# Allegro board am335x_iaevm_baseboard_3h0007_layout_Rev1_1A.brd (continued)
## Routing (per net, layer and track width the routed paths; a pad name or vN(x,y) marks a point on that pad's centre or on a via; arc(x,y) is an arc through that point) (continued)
LCD_DATA19: length 30.1
  TOP w0.121: R264.1 112.41,86.12 115,86.12 115.18,85.94 116.82,85.94 116.82,85.94 117.19,85.94 117.19,85.94 117.68,85.94 118.33,85.29 v1(118.77,85.29)
  LY3 w0.102: 130.63,79.96 131.03,79.56 133.16,79.56 133.82,78.9 J7.13
  LY3 w0.133: 130.63,79.96 129.88,80.71 129.09,80.71 126.55,83.25 126.55,85.91 125.34,87.13 122.06,87.13 120.22,85.29 v1(118.77,85.29)
LCD_DATA20: length 26.6
  TOP w0.102: 130.72,85.25 J8.3
  TOP w0.121: 130.72,85.25 130.59,85.25 130.28,84.95 128.75,84.95 128.18,85.52 128.18,87.41 127.93,87.67 125.8,87.67 122.19,84.05 112.48,84.05 112.36,83.93 112.36,83.6 112.48,83.48 112.72,83.48 112.84,83.36 112.84,83.07 112.48,82.71 R243.1
LCD_DATA21: length 35.6
  TOP w0.102: 130.72,85.89 132.12,85.89 J8.4
  TOP w0.121: R242.1 111.34,85.76 111.84,85.26 112.3,85.26 112.74,85.69 116.72,85.69 116.72,85.69 117.21,85.69 117.33,85.57 117.33,85.15 117.21,85.03 114.08,85.03 113.96,84.9 113.96,84.69 114.34,84.3 122.09,84.3 125.7,87.92 128.06,87.92 128.31,87.67 128.31,87.64 128.43,87.52 128.43,85.73 128.96,85.19 130.02,85.19 130.72,85.89
LCD_DATA22: length 50.4
  TOP w0.121: R263.1 v1(104.81,91.6)
  LY3 w0.133: v1(137.36,91.12) 138.72,91.12 139.83,90.01 139.85,90.01 139.85,89.96 v1(140.17,89.65)
  BOTTOM w0.102: 138.04,78.9 J7.14
  BOTTOM w0.121: v1(140.17,89.65) 140.17,88.83 140.12,88.78 140.12,80.99 138.04,78.9 ; v1(104.81,91.6) 107.92,91.6 108.69,90.84 124.79,90.84 125.3,90.33 128.68,90.33 129.12,90.77 132.05,90.77 132.49,90.33 136.56,90.33 137.35,91.12 v1(137.36,91.12)
LCD_DATA23: length 44.3
  TOP w0.121: v1(119.98,93.41) 110.58,93.41 108.77,91.6 R261.1 ; v1(119.34,87.72) 120.22,88.6 128.01,88.6 128.13,88.48 128.13,88.35 v1(128.89,87.59)
  LY3 w0.102: J7.11 135.11,80.17 135.04,80.25 135.04,85.13 134.81,85.36 134.81,86.52 133.92,87.41 130.72,87.41 130.54,87.59 130.21,87.59 130.14,87.67 129.78,87.67 129.74,87.63 129.64,87.63 129.6,87.59 v1(128.89,87.59)
  LY4 w0.133: v1(119.34,87.72) 119.34,92.77 v1(119.98,93.41)
LCD_DEN: length 20.6
  TOP w0.102: v1(130.01,76.36) 129.32,76.36 R273.1
  BOTTOM w0.102: 130.72,77 130.73,76.99 133.53,76.99 133.59,77.05 ; 130.72,75.71 133.44,75.71 133.57,75.58 133.57,75.14 ; 133.59,77.33 133.59,77.36 133.72,77.48 133.72,77.99 ; J8.17 130.72,76.36
  BOTTOM w0.121: 133.59,77.33 133.59,77.05 ; 133.72,77.99 133.84,78.12 134.12,78.12 134.25,77.99 134.25,75.19 134.08,75.02 133.7,75.02 133.57,75.14 ; 130.72,76.36 130.54,76.36 130.42,76.24 130.42,75.84 130.54,75.71 130.72,75.71 ; v1(130.01,76.36) 130.01,79.16 130.14,79.29 130.39,79.29 130.52,79.16 130.52,77.12 130.64,77 130.72,77
LCD_HSYNC: length 6
  TOP w0.102: 130.72,75.7 132.09,75.7 J8.18
  TOP w0.121: 130.72,75.7 130.62,75.7 130.45,75.54 130.09,75.54 129.96,75.41 129.96,75.18 130.09,75.06 130.16,75.06 130.29,74.93 130.29,74.58 130.16,74.46 129.55,74.46 129.3,74.71 R272.1
LCD_I2C_SCL: length 19.6
  TOP w0.102: 133.59,78.07 J8.14
  TOP w0.121: 146.85,71.79 146.85,72.55 146.09,73.32 140.06,73.32 139.01,74.37 138.44,74.37 138.29,74.23 135.95,74.23 134,74.23 133.59,74.64 133.59,78.07
LCD_I2C_SDA: length 17.1
  TOP w0.102: J7.15 136.56,77 138.34,77
  TOP w0.121: 138.34,77 138.72,76.62 142.02,76.62 142.99,75.65 146.44,75.65 147.23,74.87 147.23,73.67 147.35,73.55 147.35,71.03 146.85,70.52
LCD_PCLK: length 4.4
  TOP w0.102: 130.72,77 131.99,77 132.63,77.63 J8.16
  TOP w0.121: 130.72,77 128.94,77 R269.1
LCD_VSYNC: length 4.5
  TOP w0.102: 138.04,75.7 136.59,75.7 J7.17
  TOP w0.121: R271.1 138.77,74.97 138.04,75.7
LCDA_PIN18: length 2.8
  TOP w0.102: 138.04,76.36 J7.18
  TOP w0.121: R274.2 138.85,75.98 138.47,76.36 138.04,76.36
MCASP0_ACLKR: length 27.2
  TOP w0.121: v1(70.62,107.48) 71.06,107.04 77.45,107.04 R218.1
  BOTTOM w0.121: v1(70.62,107.48) 70.62,109 70.21,109.42 70.21,118.31 67.22,121.3 J6.17
MCASP0_ACLKX: length 3.2
  TOP w0.121: J6.1 R194.1
MCASP0_AHCLKR: length 21.5
  TOP w0.121: R211.2 v1(70.65,111.42)
  LY3 w0.133: v1(75.5,111.47) 72.86,111.47 72.33,110.93 71.11,110.93 70.65,111.39 v1(70.65,111.42)
  BOTTOM w0.121: v1(75.5,111.47) 74.99,111.97 74.99,118.05 72.3,120.74 J6.13
MCASP0_AHCLKX: length 20.9
  TOP w0.121: J6.27 v1(45.5,125.64) ; R234.1 v1(45.17,114.59)
  BOTTOM w0.121: v1(45.17,114.59) 45.17,119.42 45.5,119.75 v1(45.5,125.64)
MCASP0_AXR0: length 1.8
  BOTTOM w0.121: R203.2 J6.7
MCASP0_AXR1: length 3.1
  TOP w0.121: J6.23 59.47,125.51 R227.1
MCASP0_FSR: length 30.8
  TOP w0.121: v1(68.36,123.86) 63.92,123.86 J6.21 ; R224.1 73.7,102.78 v1(73.44,103.03)
  BOTTOM w0.121: v1(68.36,123.86) 68.36,121.5 72.86,117.01 72.86,104.96 73.44,104.38 v1(73.44,103.03)
MCASP0_FSX: length 1.8
  BOTTOM w0.121: R199.2 J6.5
MMC_CD: length 71.5
  TOP w0.121: v1(62.27,144.18) R378.1 64.14,144.18 U21.3 64.28,144.08 64.63,144.08 64.76,144.21 64.76,145.99 64.3,146.44 J13.15 ; R380.1 72.3,91.15 71.79,90.64 70.99,90.64 70.59,91.03 69.02,91.03 67.75,92.3 66.55,92.3 v1(66.55,92.3)
  BOTTOM w0.121: v1(62.27,144.18) 63.28,144.18 64.43,143.04 64.43,138.98 63.92,138.47 63.16,138.47 62.46,137.77 62.46,136.68 62.52,136.62 62.52,135.55 60.94,133.97 60.94,123.03 65.7,118.27 65.7,106.01 66.29,105.42 66.29,104.6 66.09,104.41 66.09,93.24 66.56,92.77 66.56,92.31 v1(66.55,92.3)
MMC_CLK: length 42.1
  TOP w0.121: v1(83.53,145.25) 83.21,144.94 82.36,144.94 81.81,144.39 81.8,144.39 81.3,143.89 77.82,143.89 77.61,143.68 72.03,143.68 71.82,143.89 66.54,143.89 65.23,142.58 61.07,142.58 60.29,141.79 57.7,141.79 57.57,141.92 57.57,142.8 57.71,142.94 U19.1 56.68,143.42 56.37,143.72 J13.5 56.3,148.58 56.3,149.78 56.18,149.9 53.15,149.9 53.03,149.78 J13.20
  BOTTOM w0.121: R398.1 83.6,145.17 v1(83.53,145.25)
MMC_CMD: length 51.3
  TOP w0.121: U19.7 58.71,145.32 v1(58.97,145.58) ; v1(48.55,147.1) 48.73,147.28 48.73,148.35 J13.2 48.88,150.06 49.6,150.79 55.34,150.79 v1(55.41,150.85) ; J13.17 v1(59.73,147.11)
  LY3 w0.133: v1(58.97,145.58) 59.55,145.58 59.65,145.68 62.8,145.68 62.97,145.51 64.08,145.51 64.76,146.19 73.95,146.19 74.59,145.55 v1(80.78,145.55)
  BOTTOM w0.121: R366.1 v1(48.55,147.1) ; v1(80.78,145.55) 81.19,145.15 R397.1 ; v1(58.97,145.58) 58.97,146.35 v1(59.73,147.11) J13.17 59.85,148.63 61.51,148.63 61.63,148.75 61.63,150.91 61.51,151.04 60.36,151.04 59.48,150.16 56.93,150.16 56.81,150.28 56.81,150.53 56.68,150.66 55.54,150.66 55.41,150.79 v1(55.41,150.85)
MMC_D0: length 47.7
  TOP w0.121: U19.2 58.13,143.34 58.13,142.96 58.01,142.84 v1(58.01,142.53) 58.44,142.1 60.03,142.1 60.77,142.84 65.14,142.84 66.44,144.13 71.93,144.13 72.13,143.93 77.51,143.93 77.99,144.41 v1(77.99,145.1) ; v1(61.38,147.1) 61.38,148.42 J13.7 61.12,148.68 61.12,149.77 61,149.9 56.67,149.9 56.43,150.14 50.96,150.14 50.53,149.71 J13.22 50.68,148.34 50.68,147.26 v1(50.84,147.1)
  BOTTOM w0.121: v1(50.84,147.1) R367.1 ; R399.1 78.02,145.1 v1(77.99,145.1) ; v1(58.01,142.53) 58.32,142.84 58.32,144.55 58.58,144.82 59.37,144.82 60.69,146.14 60.95,146.14 61.38,146.57 v1(61.38,147.1)
MMC_D1: length 42.2
  TOP w0.121: U19.3 58.71,142.66 v1(58.8,142.57) 58.94,142.43 59.88,142.43 60.31,142.86 60.31,143.63 61.89,145.21 61.89,145.83 63,146.95 J13.8 63,150.02 62.87,150.15 56.81,150.15 56.56,150.39 50.1,150.39 49.72,150.01 J13.23 49.69,148.47 v1(49.69,147.1)
  LY3 w0.133: v1(58.8,142.57) 65.35,142.57 66.68,143.89 69.73,143.89 v1(71.03,145.2)
  BOTTOM w0.121: R368.1 v1(49.69,147.1) ; R400.1 v1(71.03,145.2)
MMC_D2: length 42.7
  TOP w0.121: J13.24 v1(62.15,147.1) 62.15,146.86 v1(60.18,144.89) 59.98,144.69 U19.6 ; v1(43.85,147.1) 43.85,148.48 J13.9 43.88,149.79 44.42,150.34 46.45,150.34 47.66,151.54 57.7,151.54 v1(58.33,150.91)
  LY3 w0.133: v1(68.49,145.07) 67.63,144.21 66.51,144.21 66.44,144.14 63.3,144.14 62.55,144.89 v1(60.18,144.89)
  BOTTOM w0.121: R401.1 v1(68.49,145.07) ; v1(58.33,150.91) 59.35,151.93 61.51,151.93 62.15,151.28 v1(62.15,147.1) ; R369.1 v1(43.85,147.1)
MMC_D3: length 41.8
  TOP w0.121: J13.16 v1(60.52,147.13) 60.52,146.69 60.17,146.34 58.58,146.34 58.21,145.96 v1(58.21,145.45) U19.8 ; v1(46.38,147.12) J13.1 46.45,148.58 46.45,149.83 47.92,151.29 57.06,151.29 v1(57.44,150.91)
  LY3 w0.133: v1(66.97,145.2) 66.1,145.2 65.42,144.51 63.44,144.51 62.61,145.34 60,145.34 59.79,145.13 58.78,145.13 58.52,145.13 v1(58.21,145.45)
  BOTTOM w0.121: v1(60.52,147.13) 61.89,148.5 61.89,151.04 61.25,151.68 59.85,151.68 59.6,151.42 59.6,150.66 59.34,150.4 57.82,150.4 57.44,150.78 v1(57.44,150.91) ; R396.1 v1(66.97,145.2) ; v1(46.38,147.12) 46.38,147.85 R365.1
MMC_D4: length 49.4
  TOP w0.121: U20.1 72.71,148.87 72.71,148.6 v1(72.94,148.37) ; v1(72.17,163.23) 65.19,163.23 64.81,163.61 64.81,167.04 63.54,168.31 48.3,168.31 47.6,167.62 J13.10 v1(47.6,164.25)
  BOTTOM w0.121: v1(72.94,148.37) 72.55,148.75 72.55,152.56 72.17,152.95 v1(72.17,163.23) ; R370.1 47.6,165.2 v1(47.6,164.25)
MMC_D5: length 45.6
  TOP w0.121: U20.2 v1(73.32,149.52) ; v1(50.12,164.25) 50.12,165.48 J13.11 50.1,167.45 50.58,167.93 63.16,167.93 64.3,166.79 64.3,163.36 64.93,162.72 v1(73.06,162.72)
  BOTTOM w0.121: v1(50.12,164.25) 50.12,165.21 R371.1 ; v1(73.32,149.52) 73.32,150.28 73.06,150.53 v1(73.06,162.72)
MMC_D6: length 34.4
  TOP w0.121: v1(71.16,162.15) 63.98,162.15 63.28,162.85 63.28,166.41 62.52,167.17 57.95,167.17 57.57,166.79 57.57,166.47 57.6,166.44 J13.12 v1(57.6,164.31) ; U20.7 70.65,150.02 v1(70.52,150.15)
  BOTTOM w0.121: v1(71.16,162.15) 71.16,154.98 70.52,154.34 v1(70.52,150.15) ; R372.1 57.6,165.23 v1(57.6,164.31)
MMC_D7: length 32
  TOP w0.121: v1(70.52,149.39) 70.65,149.52 U20.8 ; v1(60.11,164.38) 60.11,165.49 J13.13 60.1,166.44 60.2,166.53 62.39,166.53 62.9,166.03 62.9,162.72 63.92,161.71 69.89,161.71 70.14,161.45 v1(71.67,161.45)
  BOTTOM w0.121: R373.1 v1(60.11,164.38) ; v1(71.67,161.45) 71.67,154.72 70.96,154.02 70.96,149.83 v1(70.52,149.39)
MMC_WP: length 58.5
  TOP w0.121: R379.1 70.52,106.46 69.71,105.65 v1(66.92,105.65) ; U21.5 65.5,145.17 v1(65.5,145.58) J13.14
  BOTTOM w0.121: v1(66.92,105.65) 66.18,106.39 66.18,118.22 62.39,122.01 62.39,124.55 63.09,125.25 63.09,126.03 62.53,126.59 62.39,126.59 61.19,127.79 61.19,129.14 61.89,129.84 61.89,133.85 64.67,136.63 64.67,144.75 v1(65.5,145.58)
NAND_ADVN_ALE: length 12.2
  TOP w0.121: R137.1 141.48,98.34 142.14,99 144.18,99 144.61,99.42 149.61,99.42 151.26,97.78 U9.17
NAND_BE0N_CLE: length 11.4
  TOP w0.121: U9.16 150.76,95.93 150.63,95.8 148.12,95.8 147.54,95.22 147.54,95.16 147.29,94.91 143.29,94.91 142.4,95.8 R136.1
NAND_CSN: length 9
  TOP w0.121: U9.9 147.26,95.5 v1(147.1,95.35) 147.04,95.29 143.42,95.29 141.64,97.07 R135.1
  BOTTOM w0.121: R132.1 v1(147.1,95.35)
NAND_D0: length 19.5
  TOP w0.121: U9.29 152.76,109.51 150.1,106.84 R140.1
NAND_D1: length 18.3
  TOP w0.121: U9.30 152.26,109.84 150.66,108.24 R141.1
NAND_D2: length 16.6
  TOP w0.121: R142.1 150.53,109.64 151.76,110.87 U9.31
NAND_D3: length 14.7
  TOP w0.121: R143.1 149.77,110.91 151.26,112.4 U9.32
NAND_D4: length 9
  TOP w0.121: U9.41 146.76,113.49 145.83,112.56 141.52,112.56 R144.1
NAND_D5: length 7.2
  TOP w0.121: U9.42 146.26,114.64 145.2,113.58 R145.1
NAND_D6: length 7
  TOP w0.121: U9.43 145.76,114.65 145.07,113.96 142.15,113.96 R146.1
NAND_D7: length 6.6
  TOP w0.121: R147.1 141.18,116.19 141.18,115.68 142.53,114.34 144.31,114.34 145.26,115.29 U9.44
NAND_D8: length 75.3
  TOP w0.121: v1(124.24,94.4) 123.69,93.85 106.68,93.85 R148.1 ; U9.26 154.26,118.4 152.36,120.3 143.16,120.3 v1(140.12,117.26)
  BOTTOM w0.121: v1(140.12,117.26) 140.12,114.21 139.17,113.26 139.17,104.94 138.85,104.62 138.85,102.86 136.19,100.2 135.69,100.2 134.7,99.22 134.7,98.16 135.17,97.7 136.05,97.7 136.94,96.81 136.94,96.18 135.93,95.16 133.64,95.16 133.32,94.84 132.43,94.84 131.99,94.4 129.39,94.4 128.94,94.84 124.69,94.84 v1(124.24,94.4)
NAND_D9: length 69.8
  TOP w0.121: v1(154.09,115.1) 153.76,115.43 U9.27 ; R149.1 105.57,93.64 106.08,94.14 123.01,94.14 124.14,95.27 127.19,95.27 127.44,95.52 128.68,95.52 131.24,98.08 136.74,98.08 138.91,100.26 143.86,100.26 144.17,100.57 153.41,100.57 154.09,99.89 v1(154.09,99.88)
  BOTTOM w0.121: v1(154.09,115.1) v1(154.09,99.88)
NAND_D10: length 71
  TOP w0.121: R150.1 110.53,88.82 116.86,88.82 117.2,89.15 128.99,89.15 129.95,90.11 131.49,90.11 132.45,89.15 143.31,89.15 144.72,90.56 149.68,90.56 150.79,91.67 151.74,91.67 153.07,93 v1(153.96,93) ; U9.28 v1(153.26,115.16)
  BOTTOM w0.121: v1(153.96,93) 153.96,97.93 153.26,98.63 v1(153.26,115.16)
NAND_D11: length 79.1
  TOP w0.102: 138.04,84.72 137.96,84.64 135.17,84.64 ; 130.77,84.7 130.82,84.64 133.59,84.64
  TOP w0.121: U9.33 v1(150.76,115.12) ; 138.04,84.72 138.82,85.51 142.29,85.51 142.48,85.7 149.95,85.7 v1(150.25,85.99) ; R151.1 109.64,82.45 109.88,82.21 112.49,82.21 114.08,83.81 122.29,83.81 125.89,87.41 127.65,87.41 127.93,87.13 127.93,85.38 128.61,84.7 130.77,84.7 ; 133.59,84.64 134.01,85.06 134.75,85.06 135.17,84.64
  BOTTOM w0.121: v1(150.25,85.99) 150.25,87.1 149.92,87.43 149.92,87.44 149.44,87.92 149.44,92.49 150.17,93.22 150.17,98.13 149.31,98.98 149.31,106.89 150.76,108.34 v1(150.76,115.12)
NAND_D12: length 64.8
  TOP w0.121: v1(148.12,90.08) 144.87,90.08 143.69,88.91 132.35,88.91 131.39,89.86 130.05,89.86 129.09,88.91 117.3,88.91 116.96,88.57 112.83,88.57 R152.1 ; v1(147.69,114.92) 147.26,115.35 U9.40
  BOTTOM w0.121: v1(147.69,114.92) 147.69,114.77 148.12,114.34 148.12,99.4 147.64,98.92 147.64,94.25 148.12,93.76 v1(148.12,90.08)
NAND_D13: length 73.4
  TOP w0.121: v1(141.13,93.38) 140.93,93.18 138.29,93.18 137.34,92.24 132.49,92.24 131.99,91.73 129.45,91.73 128.67,92.51 117.24,92.51 115.33,90.6 108.55,90.6 108.54,90.61 106.42,90.61 106.41,90.6 103.44,90.6 103.37,90.54 100.88,90.54 100.88,90.54 97.42,90.54 R153.1 ; v1(141.96,115.53) 142.52,114.97 144.56,114.97 144.76,115.17 U9.45
  BOTTOM w0.121: v1(141.13,93.38) 141.58,93.82 141.58,94.22 141.54,94.26 141.54,98.4 140.85,99.08 140.85,101.3 141.78,102.23 141.78,115.35 v1(141.96,115.53)
NAND_D14: length 66.6
  TOP w0.121: v1(143.74,101) 143.25,100.51 138.69,100.51 138.52,100.68 136.92,100.68 136.37,100.13 132.27,100.13 129.72,97.58 124.37,97.58 123.11,98.84 120.05,98.84 118.78,97.57 104.28,97.57 102.49,95.79 100.16,95.79 99.35,94.98 R154.1 ; U9.46 v1(144.26,117.46)
  BOTTOM w0.121: v1(144.26,117.46) 143.79,117 143.79,101.05 v1(143.74,101)
NAND_D15: length 66.2
  TOP w0.121: v1(137.07,102.15) 136.82,102.4 136.82,102.41 136.57,102.65 132.8,102.65 130.3,100.15 130.01,99.86 114.49,99.86 112.97,98.34 104.34,98.34 102.55,96.55 98.63,96.55 R155.1 ; v1(138.92,117.26) 139.36,116.82 141.23,116.82 142.33,117.92 143.52,117.92 143.76,117.68 U9.47
  BOTTOM w0.121: v1(138.92,117.26) 138.67,117.01 138.67,105.26 138.35,104.94 138.35,103.8 137.07,102.52 v1(137.07,102.15)
NAND_OEN: length 14.3
  TOP w0.121: v1(147.03,98.08) 146.76,97.81 U9.8 ; R134.1 v1(147.57,104.18)
  BOTTOM w0.121: v1(147.57,104.18) 147.81,103.93 147.81,99.73 147.03,98.94 v1(147.03,98.08)
NAND_WAIT: length 13.9
  TOP w0.121: R133.1 144.51,102.78 144.72,102.98 v1(147.37,102.98) ; v1(146.26,98.08) 146.25,97.91 U9.7
  BOTTOM w0.121: R131.1 146.6,97.75 v1(146.26,98.08) 146.65,98.46 146.65,99.27 147.37,100 v1(147.37,102.98)
NAND_WEN: length 18.6
  TOP w0.121: v1(150.07,105.62) 147.76,105.62 147.71,105.57 R138.1 ; v1(151.68,98.08) 151.75,98 U9.18
  BOTTOM w0.121: v1(150.07,105.62) 150.93,104.77 150.93,101.29 151.95,100.27 151.95,98.36 v1(151.68,98.08)
NAND_WPN: length 17.7
  TOP w0.121: v1(151.4,101.74) 151.4,101.13 151.27,101 148.02,101 147,102.02 141.65,102.02 R139.1 ; v1(152.44,98.08) 152.25,97.9 U9.19
  BOTTOM w0.121: v1(151.4,101.74) 152.44,100.7 v1(152.44,98.08) R130.1
PB_INTERRUPT: length 5.7
  BOTTOM w0.121: R560.1 7.02,46.39 R113.2 6.9,45.78 6.92,45.76 R156.1 6.92,42.89 6.9,42.86 C118.1
PM_ALERT: length 21.6
  TOP w0.121: v1(65.89,38.26) 63.92,36.3 63.92,35.6 63.47,35.15 U32.3
  BOTTOM w0.121: U27.3 70.9,47.03 70.65,46.77 70.65,44.87 69.63,43.85 69.63,42.46 69.25,42.07 67.22,42.07 J17.4 R455.1 65.19,40.3 65.19,39.03 65.89,38.33 v1(65.89,38.26)
PM_VDDAADCN: length 2.5
  BOTTOM w0.121: J27.2 46.01,75.35 R501.3
  BOTTOM w0.127: R501.3 46.87,75.35 47.12,75.1
PM_VDDAADCP: length 2.5
  BOTTOM w0.121: R501.4 46.01,76.11 J27.1
  BOTTOM w0.127: 47.15,76.39 46.87,76.11 R501.4
PM_VDDCOREN: length 5.9
  TOP w0.121: v1(64.68,47.79) 64.68,47.54 66.44,45.78 R32.4
  BOTTOM w0.121: v1(64.68,47.79) 65.73,47.79 65.74,47.78 65.97,47.78 66.23,47.53 U27.9
PM_VDDCOREP: length 3.5
  TOP w0.121: R32.3 67.43,48.42 v1(65.44,48.42)
  BOTTOM w0.121: U27.10 65.84,48.03 v1(65.44,48.42)
PM_VDDMPUN: length 5.1
  TOP w0.121: U32.9 68.56,35.65 70.12,34.1 R46.4
PM_VDDMPUP: length 4.7
  TOP w0.121: U32.10 68.56,36.15 69.25,36.85 R46.3
PM_VDDSDDRN: length 2.6
  TOP w0.121: R508.4 113.63,67.48 J20.2
  TOP w0.127: 113.91,68.68 113.63,68.4 R508.4
PM_VDDSDDRP: length 2.5
  TOP w0.121: R508.3 112.88,67.48 J20.1
  TOP w0.127: R508.3 112.88,68.4 112.63,68.65
PM_VDDSHV1N: length 2.7
  BOTTOM w0.121: R493.3 121.19,67.6 J26.2
  BOTTOM w0.127: 121.45,68.71 121.19,68.46 R493.3
PM_VDDSHV1P: length 2.6
  BOTTOM w0.121: R493.4 120.43,68.32 120.43,68.24 119.67,67.47 J26.1
  BOTTOM w0.127: 120.16,68.74 120.44,68.46 R493.4
PM_VDDSHV2N: length 2.5
  BOTTOM w0.121: R545.3 113.32,92.88 J38.2
  BOTTOM w0.127: 113.57,94.05 113.32,93.8 R545.3
PM_VDDSHV2P: length 2.6
  BOTTOM w0.121: J38.1 112.56,92.88 R545.4
  BOTTOM w0.127: 112.28,94.08 112.56,93.8 R545.4
PM_VDDSHV3N: length 2.5
  TOP w0.121: R546.3 131.61,139.67 J39.2
  TOP w0.127: R546.3 132.53,139.67 132.79,139.92
PM_VDDSHV3P: length 2.6
  TOP w0.121: R546.4 131.61,138.92 J39.1
  TOP w0.127: R546.4 132.53,138.92 132.81,138.64
PM_VDDSHV4N: length 3.3
  BOTTOM w0.121: J30.2 137.7,132.24 R494.3
  BOTTOM w0.127: 135.58,132.49 135.83,132.24 R494.3
PM_VDDSHV4P: length 3.5
  BOTTOM w0.121: R494.4 137.45,131.49 J30.1
  BOTTOM w0.127: R494.4 135.83,131.49 135.55,131.21
PM_VDDSHV5N: length 3.4
  BOTTOM w0.121: R495.3 101.39,144.05 J32.2
  BOTTOM w0.127: R495.3 101.39,142.31 101.13,142.05
PM_VDDSHV5P: length 3.4
  BOTTOM w0.121: J32.1 102.14,144.05 R495.4
  BOTTOM w0.127: 102.42,142.03 102.14,142.31 R495.4
PM_VDDSHV6N: length 2.3
  BOTTOM w0.121: R496.3 51.29,88.62 J34.2
  BOTTOM w0.127: 51.03,87.7 51.29,87.95 R496.3
PM_VDDSHV6P: length 2.3
  BOTTOM w0.121: R496.4 52.04,88.62 J34.1
  BOTTOM w0.127: R496.4 52.04,87.95 52.32,87.67
PM_VDDSN: length 2.9
  BOTTOM w0.121: R498.3 101.51,117.76 100.62,118.66
  BOTTOM w0.127: R498.3 101.51,116.53 101.26,116.27
PM_VDDSOSCN: length 2.9
  BOTTOM w0.121: R506.3 113.83,61.64 J29.2
  BOTTOM w0.127: R506.3 113.83,62.74 114.08,63
PM_VDDSOSCP: length 2.8
  BOTTOM w0.121: J29.1 113.07,61.38 R506.4
  BOTTOM w0.127: R506.4 113.07,62.74 112.79,63.02
PM_VDDSP: length 2.9
  BOTTOM w0.121: J21.1 102.27,117.76 R498.4
  BOTTOM w0.127: 102.55,116.25 102.27,116.53 R498.4
PM_VDDSRTCN: length 2.6
  BOTTOM w0.121: R505.3 61.69,47.28 J35.2
  BOTTOM w0.127: 61.95,48.52 61.69,48.27 R505.3
PM_VDDSRTCP: length 2.6
  BOTTOM w0.121: J35.1 60.94,47.28 R505.4
  BOTTOM w0.127: R505.4 60.94,48.27 60.66,48.55
PM_VPLLCRLCDN: length 2.9
  BOTTOM w0.121: R503.3 106.59,61.51 J24.2
  BOTTOM w0.127: 106.84,63 106.59,62.74 R503.3
PM_VPLLCRLCDP: length 2.9
  BOTTOM w0.121: J24.1 105.83,61.51 R503.4
  BOTTOM w0.127: R503.4 105.83,62.74 105.55,63.02
PM_VPLLDDRN: length 2.6
  BOTTOM w0.121: J33.2 60.87,53 R507.4
  BOTTOM w0.127: R507.4 60.87,53.98 60.59,54.26
PM_VPLLDDRP: length 2.6
  BOTTOM w0.121: J33.1 61.63,53 R507.3
  BOTTOM w0.127: R507.3 61.63,53.98 61.88,54.24
PM_VPLLMPUN: length 2.7
  TOP w0.121: J22.2 95.29,117.64 R497.4
  TOP w0.127: 95.01,116.5 95.29,116.78 R497.4
PM_VPLLMPUP: length 2.7
  TOP w0.121: J22.1 95.92,117.77 95.92,117.04 R497.3
  TOP w0.127: R497.3 96.05,116.78 96.3,116.53
PM_VSRAMCOREN: length 2.4
  BOTTOM w0.121: R500.4 46.52,102.27 J23.2
  BOTTOM w0.127: 47.91,102.55 47.63,102.27 R500.4
PM_VSRAMCOREP: length 2.6
  BOTTOM w0.121: R500.3 47.03,101.51 J23.1
  BOTTOM w0.127: 47.89,101.26 47.63,101.51 R500.3
PM_VSRAMMPUN: length 2.4
  BOTTOM w0.121: R499.4 46.9,96.55 J25.2
  BOTTOM w0.127: R499.4 47.63,96.55 47.91,96.83
PM_VSRAMMPUP: length 2.3
  BOTTOM w0.121: R499.3 46.9,95.8 J25.1
  BOTTOM w0.127: 47.89,95.54 47.63,95.8 R499.3
PM_VUSB1_8VN: length 3.4
  TOP w0.121: J28.2 115.61,143.92 R502.4
  TOP w0.127: R502.4 115.61,142.18 115.33,141.9
PM_VUSB1_8VP: length 3.4
  TOP w0.121: J28.1 116.37,143.92 R502.3
  TOP w0.127: 116.62,141.93 116.37,142.18 R502.3
PM_VUSB3_3VN: length 3.4
  TOP w0.121: R504.4 108.5,143.92 J31.2
  TOP w0.127: R504.4 108.5,142.18 108.22,141.9
PM_VUSB3_3VP: length 3.4
  TOP w0.121: J31.1 109.25,143.92 R504.3
  TOP w0.127: 109.51,141.93 109.25,142.18 R504.3
PMIC_DELAYEDRTCPORZ: length 1.8
  TOP w0.121: U1.6 65.44,99.86 R3.1
PMIC_GPIO: length 129.9
  TOP w0.121: R3.2 66.92,99.35 66.41,98.84 64.66,98.84 64.16,98.34 63.8,98.34 63.4,98.74 61.04,98.74 v1(60.87,98.57) ; v1(82.21,37.51) 80.67,37.51 78.51,39.67 56.62,39.67 v1(56.5,39.79) ; v1(78.02,29.5) 78.02,27.98 79.51,26.48 80.98,26.48 81.46,26.96 85.89,26.96 86.4,26.45 86.4,25.7 86.79,25.31 92.06,25.31 92.95,24.42 94.27,24.42 94.53,24.17 R69.1 C114.1
  BOTTOM w0.121: v1(56.5,39.79) 57.57,40.86 57.57,57.19 58.46,58.08 58.46,69.06 61.42,72.03 62.37,72.98 62.37,80.86 61.99,81.25 61.99,81.29 61.96,81.32 61.96,82.74 61.32,83.38 61.32,86.29 60.89,86.72 60.6,87.01 60.6,87.42 60.6,88.01 59.46,89.15 59.46,89.15 59.46,96.93 60.87,98.34 v1(60.87,98.57) ; v1(78.02,29.5) 78.02,30.14 78.78,30.9 80.56,30.9 81.06,31.41 81.06,33.95 82.59,35.47 82.59,37.13 v1(82.21,37.51)
PMIC_I2C_SCL: length 149.2
  TOP w0.121: v1(140.58,58.28) 140.07,57.77 132.87,57.77 131.8,58.84 129.08,58.84 129.01,58.9 122.79,58.9 122.08,58.2 v1(121.58,58.2) ; v1(141.54,99.02) 141.36,98.84 138.89,98.84 137.97,97.91 137.97,96.43 137.08,95.54 132.37,95.54 131.54,94.71 131.54,94.63 131.23,94.31 R55.1
  TOP w0.203: U4.9 90.45,29.95 90.84,29.55 v1(90.84,28.99)
  LY3 w0.133: v1(90.84,28.99) 90.84,28.55 88.81,26.52 v1(85.36,26.52)
  BOTTOM w0.121: R551.1 84.26,25.06 85.36,26.15 v1(85.36,26.52) ; v1(140.58,58.28) 140.58,58.71 140.6,58.74 140.6,65.94 141.38,66.72 141.38,71.57 143.29,73.47 143.29,87.44 142.29,88.44 142.29,93.49 141.82,93.95 141.82,94.3 141.81,94.31 141.81,98.48 141.54,98.75 v1(141.54,99.02) ; v1(90.84,28.99) 91.21,28.99 93.05,27.15 95.41,27.15 101.38,21.18 106.65,21.18 106.67,21.2 106.77,21.2 109.13,23.57 109.13,25.44 112.37,28.68 112.37,38.14 121.07,46.84 121.07,57.7 v1(121.58,58.2)
PMIC_I2C_SDA: length 115.2
  TOP w0.121: v1(60.68,93.76) 60.68,94.43 61.04,94.79 63.92,94.79 64.76,93.95 65.55,93.95 66.07,93.43 66.24,93.43 66.41,93.26 67.85,93.26 68.36,92.75 R56.1 ; v1(90.21,29.5) 90.05,29.66 U4.8 ; v1(84.44,26.52) 84.25,26.71 81.56,26.71 81.05,26.2 79.31,26.2 74.48,31.03 v1(57.7,31.03)
  LY3 w0.133: v1(90.21,29.5) 87.92,27.22 85.14,27.22 v1(84.44,26.52)
  BOTTOM w0.121: v1(84.44,26.52) 84.12,26.2 R550.1 ; v1(60.68,93.76) 59.96,93.04 59.96,89.36 61.1,88.22 61.1,87.21 61.82,86.49 61.82,83.58 62.45,82.95 62.45,81.54 62.48,81.51 62.48,81.5 62.53,81.44 62.53,81.4 62.87,81.07 62.87,72.77 62.21,72.11 59.41,69.31 59.41,58.65 57.82,57.06 57.82,35.98 57.44,35.6 57.44,34.58 57.7,34.33 v1(57.7,31.03)
PMIC_INTN: length 132.5
  TOP w0.121: U4.45 v1(85.52,32.69) ; v1(55.33,42.53) 55.56,42.3 58.81,42.3 59.74,41.38 71.4,41.38 71.98,40.8 79.03,40.8 v1(79.67,40.17) ; R66.1 79.79,102.65 80.3,103.16 80.3,106.13 78.04,108.39 66.71,108.39 66.04,107.72 60.96,107.72 v1(60.49,107.25)
  BOTTOM w0.121: v1(60.49,107.25) 59.12,105.88 59.12,103.16 57.98,102.02 57.98,90.18 57.98,88.53 58.27,88.24 58.56,87.95 58.81,87.7 59.1,87.41 59.1,86.32 59.84,85.58 59.84,82.76 60.47,82.13 60.47,81.29 60.47,72.96 57.17,69.65 57.17,68.57 57.17,58.69 56.34,57.86 56.34,43.53 v1(55.33,42.53) ; v1(85.52,32.69) 85.52,33.23 85.79,33.49 85.79,35.64 82.55,38.87 80.96,38.87 v1(79.67,40.17)
PMIC_PWR_EN: length 206.4
  TOP w0.102: v2(79.4,81.8) U2.C6
  TOP w0.121: v1(134.89,46.87) 133.77,45.76 109.71,45.76 108.64,46.83 106.17,46.83 105.6,47.41 89.11,47.41 88.48,46.77 80.5,46.77 v1(79.87,47.41) 73.7,47.41 72.83,48.28 72.59,48.28 71.82,49.06 70.14,49.06 69.51,49.69 66.84,49.69 66.08,48.93 65.12,48.93 64.93,48.74 v1(64.43,48.74) ; v1(136.94,93.51) 137.6,94.17 139.19,94.17 140.04,95.02 142.65,95.02 143.32,94.35 143.57,94.35 v1(144.41,93.51)
  BOTTOM w0.102: 77.1,80.69 77.96,81.55 79.15,81.55 v2(79.4,81.8)
  BOTTOM w0.121: v1(136.94,93.51) 135.91,92.47 133.83,92.47 133.76,92.55 132.76,92.55 132.69,92.47 131.76,92.47 R178.1 ; R556.2 86.04,32.07 86.04,35.83 82.59,39.28 81.18,39.28 78.52,41.94 78.52,46.06 v1(79.87,47.41) ; v1(134.89,46.87) 134.96,46.95 134.96,49.86 144.41,59.31 v1(144.41,93.51) ; 77.1,80.69 77.08,80.69 76.73,80.34 76.25,80.34 76.06,80.15 73.96,80.15 73.91,80.1 72.3,80.1 72.25,80.15 70.24,80.15 69.38,79.29 69.38,72.3 66.97,69.89 66.97,67.79 66.65,67.47 66.65,64.36 65.7,63.41 65.7,61.57 66.71,60.55 66.71,59.09 66.2,58.58 65.44,58.58 65.06,58.2 65.06,57.19 65.38,56.87 65.38,49.7 v1(64.43,48.74)
PMIC_PWRHOLD: length 3.6
  TOP w0.121: v1(86.52,29.93) 86.57,29.93 86.91,30.26 86.91,30.47 87.15,30.72 U4.1
  BOTTOM w0.121: v1(86.52,29.93) 86.48,29.93 86.02,30.4 R556.1
PMIC_RESETOUTN: length 98.3
  TOP w0.121: R1.2 59.35,99.1 v1(59.27,99.02) ; U4.40 85.65,34.69 85.57,34.77 84.94,34.77 v1(84.49,34.33) 84.34,34.48 84.34,37.78 83.86,38.26 80.27,38.26 78.37,40.17 71.69,40.17 71,40.85 56.83,40.85 v1(56.5,40.52)
  BOTTOM w0.121: v1(59.27,99.02) 59.27,98.06 58.97,97.75 58.97,89.77 58.97,88.94 60.11,87.8 60.11,86.71 60.52,86.3 60.83,85.99 60.83,83.17 61.46,82.54 61.46,72.42 58.21,69.16 58.21,58.21 57.33,57.33 57.33,41.35 v1(56.5,40.52) ; R65.2 v1(84.49,34.33)
PMIC_SLEEP: length 124.3
  TOP w0.121: v1(55.94,41.39) 56.01,41.46 58.46,41.46 58.82,41.1 71.33,41.1 71.9,40.54 78.35,40.54 80.37,38.51 83.99,38.51 84.75,37.76 84.75,36.87 85.72,35.89 U4.37 ; R62.1 78.65,102.6 77.6,103.65 77.6,104.02 78.04,104.46 v1(78.4,104.46)
  LY3 w0.133: v1(60.36,103.92) 61.14,104.7 68.12,104.7 68.19,104.76 70.24,104.76 70.59,104.41 77.39,104.41 77.72,104.75 78.1,104.75 v1(78.4,104.46)
  BOTTOM w0.121: v1(55.94,41.39) 56.83,42.28 56.83,57.59 57.66,58.43 57.66,69.45 60.68,72.46 60.97,72.75 60.97,82.33 60.33,82.97 60.33,85.79 60.03,86.09 59.6,86.53 59.6,87.62 58.76,88.45 58.47,88.74 58.47,99.47 60.36,101.35 v1(60.36,103.92)
PMICSR_I2C_SCL: length 97.1
  TOP w0.121: v1(119.67,60.04) 119.67,62.44 125.89,68.67 137.26,68.67 137.39,68.79 137.39,71.03 138.28,71.92 138.85,71.92 139.42,72.49 140.56,72.49 140.88,72.81 143.8,72.81 R58.1
  TOP w0.203: U4.11 91.25,30.11 91.37,29.99 91.75,29.99 v1(93.26,28.49)
  BOTTOM w0.121: v1(119.67,60.04) 120.12,59.59 120.12,46.96 111.61,38.45 111.61,28.81 108.64,25.83 108.64,23.8 106.53,21.69 101.82,21.69 95.35,28.17 93.57,28.17 v1(93.26,28.49)
PMICSR_I2C_SDA: length 95.3
  TOP w0.121: v1(121.1,59.85) 121.13,59.89 121.13,62.28 126.53,67.68 143.88,67.68 144.82,68.62 R59.1
  TOP w0.203: v1(92.44,28.38) 92.44,28.64 91.71,29.37 91.48,29.37 90.85,30.01 U4.10
  BOTTOM w0.121: v1(121.1,59.85) 121.1,58.93 120.37,58.2 120.37,46.84 111.86,38.33 111.86,28.69 108.89,25.71 108.89,23.67 106.66,21.45 101.72,21.45 95.24,27.92 92.88,27.92 92.44,28.36 v1(92.44,28.38)
PORZ: length 3.1
  TOP w0.121: R9.1 R2.2 65.69,100.36 U1.7
PWR_SMPS1: length 5.2
  TOP w0.121: 87.65,36.77 U4.35
  TOP w0.203: 87.65,36.77 87.65,37.52 87.54,37.63
  TOP w0.508: 87.54,37.63 87.54,39.15 86.83,39.87 85.13,39.87
PWR_SMPS1_FB: length 51.7
  TOP w0.203: 88.73,38.54 88.73,37.88 88.85,37.77 U4.32
  TOP w0.381: R562.2 88.81,39.66 v1(88.43,39.28) 88.43,38.85 88.73,38.54 ; 72.68,78.27 v1(72.05,78.27)
  LY4 w0.381: v1(88.43,39.28) 88.43,44.49 81.44,51.47 81.44,59.35 82.97,60.87 82.97,65.44 80.7,67.71 80.16,67.71 73.33,74.53 73.33,75.08 73.32,75.09 73.32,77 v1(72.05,78.27)
PWR_SMPS2: length 4.4
  TOP w0.203: 85.51,33.69 85.71,33.89 U4.42
  TOP w0.381: 85.51,33.69 83.22,33.69 83.02,33.9 L3.1
PWR_SMPS3: length 4.3
  TOP w0.203: U4.31 89.25,38.27 89.57,38.59 89.57,39.03
  TOP w0.508: 89.57,39.03 90.23,39.68 90.23,40.48 L8.1
PWR_SWIO: length 3.2
  TOP w0.203: L4.1 94.84,31.89 93.19,31.89 93.17,31.91 92.83,31.91 92.81,31.89 U4.14
PWR_VAUX1: length 4.8
  TOP w0.203: U4.46 85.81,32.29 85.68,32.16 85.67,32.16 85.6,32.09 85.2,32.09
  TOP w0.508: R474.1 v1(84.62,30.77) 84.62,31.51 85.2,32.09
  BOTTOM w0.508: C109.1 v1(84.62,30.77)
PWR_VAUX2: length 5.3
  TOP w0.203: 86.37,31.39 U4.48 ; 86.37,31.39 86.37,31.49 ; 86.37,31.39 86.37,30.74
  TOP w0.508: R475.1 v1(84.62,29.25) 85.38,29.25 85.88,29.75 85.88,30.13 85.89,30.14 85.89,30.27 86.37,30.74
  BOTTOM w0.508: C110.1 v1(84.62,29.25)
PWR_VAUX33: length 6.1
  TOP w0.203: U4.4 88.45,30.11 88.35,30.02 88.35,29.72 88.18,29.54 88.18,29.25 87.82,28.89 87.82,28.74 v1(87.67,28.59)
  TOP w0.508: v1(94.14,28.61) 94.64,28.61 R466.1
  TOP w0.635: R466.1 R463.2
  BOTTOM w0.508: C108.1 v1(87.67,28.59)
PWR_VDAC: length 2
  TOP w0.508: R471.1 v1(95.97,36.11)
  BOTTOM w0.508: v1(95.97,36.11) 96.1,36.23 C101.1
PWR_VDD1_SMPS: length 9.5
  TOP w0.508: 88.63,43.27 L2.2 83.22,43.27 82.14,42.19 R469.2
  BOTTOM w0.508: C237.1 v1(85.87,45.11)
PWR_VDD2_SMPS: length 14.5
  TOP w0.203: 84.61,33.17 85.72,33.17 85.81,33.09 U4.44
  TOP w0.381: 84.37,32.93 84.61,33.17
  TOP w0.508: R468.2 79.12,35.21 L3.2 79.62,32.34 80.17,31.79 83.86,31.79 84.37,32.3 84.37,32.93
  BOTTOM w0.508: v1(78.02,33.82) 78.38,34.18 C239.1
PWR_VDD3_SMPS: length 1.4
  TOP w0.203: 89.65,36.67 89.65,38.08
  vias: v1(90.36,38.67)
PWR_VDDIO: length 8.5
  TOP w0.203: 91.73,30.64 91.76,30.62 ; 91.76,30.62 91.65,30.62 ; 91.76,30.62 92.44,30.62 92.72,30.34
  TOP w0.762: R465.2 R466.2 96.95,28.98 96.63,29.3 95.06,29.3 94.93,29.42 93.64,29.42 92.72,30.34
PWR_VDIG1: length 5
  TOP w0.203: 89.65,30.72 89.65,28.92 v1(89.95,28.61)
  BOTTOM w0.635: v1(89.95,28.61) 89.72,28.61 89.45,28.34 C104.1 89.51,27.66 90.92,27.66 R464.2
PWR_VDIG2: length 4.8
  TOP w0.203: C103.1 88.18,28.36 88.68,28.86 88.68,29.88 88.85,30.04 U4.5
  TOP w0.635: C103.1 89.31,27.72 R476.2
PWR_VIO_SMPS: length 8.8
  TOP w0.203: U4.16 93.19,32.69 v1(93.46,32.42)
  BOTTOM w0.508: v1(93.46,32.42) 95.8,32.42 96.54,31.68 C241.1 100.73,31.68 v1(100.75,31.66)
PWR_VMMC: length 3.4
  TOP w0.508: C107.1 86.14,27.72
  TOP w0.762: 86.14,27.72 R477.2
PWR_VPLL: length 6.7
  TOP w0.203: 92.52,35.89 92.52,36.51
  TOP w0.381: 92.52,36.51 92.75,36.74 94.73,36.74 v1(95.87,37.88)
  TOP w0.508: R473.1 v1(95.87,37.88)
  BOTTOM w0.508: C102.1 v1(95.87,37.88)
PWRMON_I2CSCL: length 23.6
  TOP w0.121: v1(73.51,38.14) 70.65,38.14 69.99,37.47 66.46,37.47 65.98,36.99 65.89,36.99 64.81,35.91 64.81,34.71 64.25,34.15 U32.5
  BOTTOM w0.121: v1(73.51,38.14) 72.94,38.71 72.94,40.8 R453.1 J17.1 73.57,44.74 73.32,45 72.94,45 72.27,45.66 72.27,45.77 72.01,46.03 U27.5
PWRMON_I2CSDA: length 19.7
  TOP w0.121: U32.4 63.93,34.65 64.43,35.15 64.43,36.23 65.63,37.44 66.07,37.44 66.36,37.72 69.6,37.72 v1(70.01,38.14)
  BOTTOM w0.121: U27.4 71.16,46.53 70.9,46.27 70.9,45.63 71.03,45.5 J17.2 R454.1 70.33,40.61 70.33,38.45 v1(70.01,38.14)
RS232_CTS: length 15.3
  TOP w0.121: U18.8 v1(108.6,14.13)
  BOTTOM w0.121: J12.8 117.27,11.71 114.85,14.13 v1(108.6,14.13)
RS232_RTS: length 15.2
  TOP w0.121: U18.7 v1(108.62,15.4)
  BOTTOM w0.121: v1(108.62,15.4) 107.73,14.52 107.73,13.37 108.75,12.36 113.32,12.36 114.5,11.17 J12.7
RS232_RXD: length 10.8
  TOP w0.121: U18.13 113.26,19.21 113.6,18.87 113.6,17.03 113.96,16.67 113.96,11.25 J12.2
RS232_TXD: length 13
  TOP w0.121: U18.14 114.08,20.48 115.1,19.47 115.1,11.2 J12.3
RTCK: length 2.8
  TOP w0.121: J2.9 v1(22.14,91.73)
  BOTTOM w0.121: v1(22.14,91.73) R74.1
SDIO_GPMC_A1: length 1.1
  TOP w0.121: R196.2 85.25,121.45 85.13,121.32
SDIO_GPMC_A2: length 1.1
  TOP w0.121: R575.1 82.84,121.45 R198.2
SDIO_GPMC_A3: length 1.1
  TOP w0.121: R202.2 80.3,121.45 R576.1
SDIO_GPMC_BE1N: length 1.2
  TOP w0.121: R186.2 97.55,143.7 R577.1
SDIO_GPMC_CLK: length 1.2
  TOP w0.121: R181.2 R572.1
SDIO_GPMC_CS3N: length 1.1
  TOP w0.121: R187.2 93.92,143.75 R573.1
SYS_RESETN: length 295.6
  TOP w0.102: 77.1,85.79 77.49,85.4 U2.A10
  TOP w0.121: 77.1,85.79 76.83,85.79 75.85,86.77 75.23,86.77 73.85,88.15 72.72,88.15 71.48,86.91 70.47,86.91 69.63,87.75 R10.2 69.23,88.9 69.05,88.9 67.76,90.19 65.92,90.19 65.66,89.94 65.65,89.94 65.43,89.71 65.29,89.71 65.29,89.71 63.75,89.71 63.36,90.1 60.29,90.1 59.98,90.4 56.69,90.4 55.28,91.81 48.82,91.81 47.11,90.09 32.94,90.09 32.55,89.7 32.55,86.14 31.15,84.75 24.68,84.75 v1(24.17,84.24) 23.98,84.05 23.21,84.05 22.32,84.94 21.05,84.94 20.48,85.51 R517.2 ; v1(134.56,51.57) 130.95,51.57 128.18,48.8 116.12,48.8 115.24,47.92 88.81,47.92 88.17,47.28 80.97,47.28 80.15,48.1 73.71,48.1 73.03,48.77 72.8,48.77 72.31,49.26 72.02,49.55 70.35,49.55 70,49.9 69.71,50.19 66.63,50.19 65.9,49.45 55.47,49.45 55.24,49.69 45.15,49.69 39.31,43.85 29.76,43.85 29.37,44.23 19.85,44.23 17.56,46.52 v1(17.56,51.29) ; J3.26 134.17,92.98 137.04,92.98 137.98,93.92 139.3,93.92 140.15,94.77 141.38,94.77 142.05,94.1 v1(142.3,94.1)
  BOTTOM w0.121: 24.17,87.92 24.68,87.41 24.68,84.75 v1(24.17,84.24) 23.07,83.15 23.07,67.98 20.87,65.78 20.87,63.84 21.35,63.36 21.35,61.61 17.56,57.82 v1(17.56,51.29) ; v1(142.3,94.1) 142.53,93.87 142.53,88.55 143.55,87.53 143.55,73.32 141.63,71.4 141.63,58.65 v1(134.56,51.57)
SYS_WARMRESETN: length 243
  TOP w0.121: v1(10.8,66.86) SW2.4 SW2.3 10.88,59.35 C117.1 ; v1(123,115.33) 118.15,115.33 117.41,114.59 93.72,114.59 91.36,116.96 66.66,116.96 65.78,117.83 41.51,117.83 40.65,116.98 29.76,116.98 28.13,115.35 26.21,115.35 v1(26.15,115.29) ; R10.1 68.1,89.01 68.1,89.5 67.66,89.94 66.02,89.94 65.77,89.69 65.76,89.69 65.53,89.46 65.4,89.46 65.39,89.46 60.03,89.46 59.33,90.16 56.27,90.16 54.87,91.56 48.93,91.56 47.21,89.85 33.84,89.85 32.85,88.86 32.85,85.91 31.33,84.38 26.85,84.38 26.27,83.8 23.12,83.8 23.05,83.86 22.53,84.38 18.2,84.38 16.24,86.35 v1(10.96,86.35)
  BOTTOM w0.121: J4.11 128.18,111.72 126.94,112.97 126.94,114.95 126.55,115.33 v1(123,115.33) ; v1(26.15,115.29) 26.23,115.2 26.23,103.15 21.8,98.72 13.25,98.72 11.47,96.94 11.47,86.85 v1(10.96,86.35) 10.96,84.24 11.09,84.11 11.09,67.14 v1(10.8,66.86)
TCK: length 2.8
  TOP w0.121: J2.11 v1(22.14,90.46)
  BOTTOM w0.121: v1(22.14,90.46) R75.1
TSC_CLK: length 48.8
  TOP w0.095: 50.96,60.49 49.19,60.49 J9.5
  TOP w0.121: v1(60.87,92.01) 61.28,91.6 R250.1 ; v1(60.11,60.49) 50.96,60.49
  BOTTOM w0.121: v1(60.11,60.49) 60.11,69.31 63.36,72.57 63.36,81.31 62.98,81.7 62.98,82.94 62.31,83.61 62.31,86.7 61.59,87.42 61.59,87.53 61.59,88.42 60.45,89.56 60.45,91.62 60.84,92.01 v1(60.87,92.01)
TSC_GIO0: length 6
  TOP w0.121: TP38.1 44.11,61.38 46.39,63.66 J9.1
TSC_GIO1: length 6.1
  TOP w0.121: TP39.1 44.49,59.98 46.9,62.39 J9.3
TSC_GIO2: length 115
  TOP w0.121: v1(49.59,136.44) 51.04,134.99 53.77,134.99 54.58,134.17 60.26,134.17 62.44,131.99 R255.1
  BOTTOM w0.121: 49.82,59.85 50.96,61 50.96,64.3 49.73,65.53 47.68,65.53 41.59,71.61 41.59,79.41 44.38,82.2 44.38,91.83 43.91,92.3 43.91,92.5 43.9,92.5 43.9,93.9 43.83,93.98 43.83,96.18 43.71,96.3 43.71,98.02 43.97,98.29 44.56,98.88 44.56,103.46 44.59,103.48 44.59,104.79 47.38,107.58 50.66,107.58 51.14,108.06 51.14,115.96 50.58,116.52 50.58,133.92 49.59,134.91 v1(49.59,136.44)
TSC_I2CSCL: length 71.3
  TOP w0.121: v1(43.06,94.12) 44.39,94.12 44.84,93.66 47.36,93.66 47.8,94.1 50.79,94.1 53.04,96.34 57.39,96.34 58.68,97.63 61.32,97.63 61.68,98 63.09,98 63.49,97.6 64.47,97.6 64.97,98.09 70,98.09 70.29,97.8 71.79,96.3 R244.1
  BOTTOM w0.121: 49.82,62.39 50.68,63.26 50.68,64.08 49.73,65.04 47.66,65.04 41.34,71.36 41.34,79.69 44.08,82.43 44.08,91.78 43.66,92.2 43.66,92.39 43.66,92.4 43.66,93.53 v1(43.06,94.12)
TSC_I2CSDA: length 2.6
  TOP w0.121: 52.23,61.51 51.6,61.51 51.22,61.12 49.82,61.12
TSC_RSV0: length 5.9
  TOP w0.121: J9.7 47.15,59.85 45.12,57.82 TP40.1
TSC_RSV1_VREF: length 6
  TOP w0.381: J9.9 47.15,58.58 45,56.43 TP41.1
UART0_CTSN: length 192.6
  TOP w0.121: v1(61.58,107.28) 66.1,107.28 66.94,108.11 77.97,108.11 79.21,106.87 79.21,104.1 R364.1 ; U18.9 110.53,14.13 110.27,13.88 110.27,12.99 109,11.72 102.02,11.72 99.97,9.67 96.08,9.67 92.98,6.56 60.03,6.56 59.04,5.57 53.23,5.57 v1(52.69,6.11)
  BOTTOM w0.121: v1(52.69,6.11) 52.69,7.04 52.7,7.05 52.7,22.87 55.81,25.99 55.81,39.73 55.5,40.04 55.5,41.57 56.58,42.66 56.58,57.7 57.42,58.53 57.42,69.55 60.72,72.85 60.72,80.82 60.72,82.23 60.09,82.87 60.09,85.69 59.35,86.42 59.35,87.51 58.66,88.2 58.23,88.64 58.23,88.64 58.23,99.62 59.69,101.08 59.69,105.38 v1(61.58,107.28)
UART0_RTSN: length 188.2
  TOP w0.121: R362.1 79.03,101.38 79.03,102.55 78.9,102.68 78.9,102.7 78.09,103.51 78.09,103.79 v1(78.04,103.84) ; v1(53.49,6.02) 58.83,6.02 59.63,6.81 92.87,6.81 95.98,9.92 99.83,9.92 102.02,12.1 108.88,12.1 110.02,13.25 110.02,15.02 110.4,15.4 U18.10
  LY3 w0.133: v1(61.15,104) 67.96,104 68.39,103.57 75.32,103.57 75.91,104.15 77.72,104.15 v1(78.04,103.84)
  BOTTOM w0.121: v1(53.49,6.02) 53.49,6.88 52.95,7.43 52.95,22.77 56.06,25.88 56.06,40.71 57.08,41.73 57.08,57.46 57.92,58.3 57.92,69.22 61.22,72.52 61.22,82.44 60.58,83.07 60.58,85.89 60.13,86.34 60.13,86.34 59.84,86.63 59.84,87.72 58.72,88.84 58.72,88.84 58.72,99.31 61.15,101.74 v1(61.15,104)
UART0_RXD: length 204
  TOP w0.121: v1(77.18,99) 77.18,98.91 78.02,98.08 R363.1 ; v1(49.74,7.23) 50.67,7.23 50.68,7.24 53.84,7.24 54.52,6.56 58.53,6.56 59.4,7.42 92.64,7.42 95.64,10.42 99.19,10.42 101.51,12.74 108.42,12.74 109.38,13.7 109.38,17.18 110.15,17.94 U18.12 ; v1(44.68,93.13) 47.17,93.13 47.9,93.85 52.74,93.85 53.38,94.49 55.88,94.49 58.78,97.39 61.42,97.39 61.78,97.75 62.98,97.75 63.39,97.35 64.57,97.35 65.07,97.85 66.58,97.85 69.9,97.85 71.95,95.8 72.76,95.8 73.28,96.32 76.95,96.32 77.14,96.13 v1(77.14,96.1)
  BOTTOM w0.121: v1(49.74,7.23) 49.44,7.53 49.44,44.87 51.09,46.52 51.09,51.1 52.46,52.47 52.46,60.67 52.17,60.96 52.17,65.24 50.17,67.25 48.25,67.25 42.87,72.62 42.87,78.9 44.25,80.28 44.87,80.91 44.87,92.49 44.68,92.69 v1(44.68,93.13) ; v1(77.18,99) 77.18,99 76.88,98.69 76.88,96.48 77.14,96.21 v1(77.14,96.1)
UART0_TXD: length 196.4
  TOP w0.121: U18.11 110.02,16.67 109.64,16.29 109.64,13.49 108.63,12.48 101.76,12.48 99.45,10.17 95.74,10.17 92.75,7.17 59.5,7.17 58.63,6.31 54.42,6.31 53.73,7 51.04,7 50.71,6.67 v1(49.19,6.67) ; R361.1 70.52,98.34 64.87,98.34 64.37,97.84 63.59,97.84 63.19,98.25 61.58,98.25 61.21,97.88 56.42,97.88 55.74,98.56 44.87,98.56 v1(44.16,97.85)
  BOTTOM w0.121: v1(44.16,97.85) 44.16,92.41 44.63,91.94 44.63,81.01 42.62,79.01 42.62,72.41 48.12,66.91 49.88,66.91 51.93,64.86 51.93,60.86 52.13,60.65 52.13,52.49 50.84,51.2 50.84,46.65 49.19,45 v1(49.19,6.67)
USB0_CONN_DM: length 6.6
  TOP w0.114: L5.3 132.54,160.39 132.4,160.54 132.4,160.97 132.32,161.05 132.32,161.42 132.37,161.47 U23.2 132.37,162.06 132.12,162.32 131.43,162.32 131.18,162.57 131.18,164.78 131.37,164.97 J14.2
USB0_CONN_DP: length 6.4
  TOP w0.114: J14.3 130.72,164.96 130.9,164.78 130.9,162.46 131.47,161.89 131.86,161.89 U23.1 131.87,161.47 132.04,161.3 132.04,160.98 131.69,160.63 L5.4
USB0_DM: length 96.9
  TOP w0.114: U2.N18 87.96,91.96 87.96,93.74 90.33,96.11 90.33,97.19 91.25,98.11 91.25,99.32 92.11,100.18 92.11,102.73 94.12,104.74 107.46,104.74 108.3,105.57 111.8,105.57 112.5,104.87 v1(112.69,104.87) ; L5.2 132.54,157.9 132.26,157.61 132.26,156.71 v1(132.54,156.43)
  BOTTOM w0.114: v1(132.54,156.43) 132.54,156.41 132.24,156.12 132.24,154.22 122.01,143.98 122.01,135.86 116.62,130.48 116.62,126.76 114.85,124.99 114.85,108.86 112.5,106.52 112.5,105.05 v1(112.69,104.87)
USB0_DP: length 96.7
  TOP w0.114: v1(111.92,104.81) 111.44,105.29 108.42,105.29 107.58,104.46 94.23,104.46 92.39,102.61 92.39,100.06 91.53,99.2 91.53,98 90.61,97.08 90.61,96 88.24,93.63 88.24,91.85 88.24,91.84 88.24,91.25 87.99,91 U2.N17 ; L5.1 131.69,157.9 131.98,157.61 131.98,156.71 v1(131.7,156.43)
  BOTTOM w0.114: v1(131.7,156.43) 131.96,156.16 131.96,154.33 121.73,144.09 121.73,135.98 116.34,130.59 116.34,126.88 114.57,125.1 114.57,108.98 112.22,106.64 112.22,105.11 v1(111.92,104.81)
USB0_ID: length 114.9
  TOP w0.102: U2.P16 v2(89,90.6)
  TOP w0.121: v1(116.56,102.02) 116.12,102.02 115.98,101.88 113.39,101.88 113.09,101.58 108.3,101.58 106.78,103.09 96.36,103.09 94.76,101.49 94.76,98.34 93.51,97.09 v1(93.51,96.56) ; J14.4 130.07,164.44 130.09,164.42 130.09,164.1 v1(129.75,163.77) 130.64,162.88 130.64,159.09 R571.1 128.94,157.39 v1(128.94,149.33) ; v1(132.88,161.2) 132.88,161.87 U23.3 133.95,161.88 R381.2
  LY3 w0.133: v1(129.75,163.77) 130.31,163.77 v1(132.88,161.2)
  BOTTOM w0.102: v2(89,90.6) 89.64,91.24 89.64,92.9
  BOTTOM w0.121: v1(116.56,102.02) 116.56,124.94 118.72,127.1 118.72,131.95 122.77,136 122.77,144.06 128.04,149.33 v1(128.94,149.33) ; v1(93.51,96.56) 93.5,96.56 93.06,96.12 91.74,96.12 89.64,94.01 89.64,92.9
USB0_MEAS_IDN: length 2.8
  TOP w0.121: Q5.G 125.56,161.89 R565.1 R566.1
USB0_OVRCURN: length 67.8
  TOP w0.121: v1(98.94,150.18) 99.81,151.04 119.14,151.04 121.93,148.25 136.94,148.25 137.32,148.63 U22.5 138.71,149.95 R382.2 ; R384.2 92.44,133.12 v1(92.44,132.78)
  BOTTOM w0.121: v1(92.44,132.78) 91.53,133.69 91.53,134.53 90.37,135.69 90.37,142.49 92.29,144.41 92.29,146.77 95.69,150.18 v1(98.94,150.18)
USB1_CONN_DM: length 6.9
  TOP w0.114: J18.2 146.34,164.4 146.34,162.61 146.73,162.22 146.73,161.71 146.99,161.45 147.68,161.45 147.93,161.2 U30.2 147.93,160.61 147.88,160.55 147.88,160.18 147.95,160.11 147.95,159.68 148.1,159.53 L6.3
USB1_CONN_DP: length 7
  TOP w0.114: L6.4 147.25,159.77 147.6,160.11 147.6,160.44 147.43,160.61 U30.1 147.42,161.02 147.03,161.02 146.46,161.59 146.46,162.1 146.06,162.49 146.06,163.9 J18.3
USB1_DM: length 121.3
  TOP w0.102: 89.4,92.9 U2.R18
  TOP w0.114: 89.4,92.9 89.4,93.11 90.08,93.79 v1(90.08,93.83) ; v1(97.75,124.4) 98.08,124.73 98.08,125.1 98.44,125.45 124.81,125.45 124.97,125.6 137.49,125.6 138.47,124.62 139.99,124.62 v1(140.12,124.5) ; L6.2 148.1,157.03 147.81,156.75 147.81,155.61 149.22,154.2 149.22,151.83 v1(149.51,151.55)
  BOTTOM w0.114: v1(90.08,93.83) 90.27,93.64 91.77,93.64 93.14,95.01 94.5,95.01 95.69,96.2 95.69,101.52 97.62,103.45 97.62,116.12 98.31,116.8 98.31,119.75 97.6,120.46 97.6,123.44 98.03,123.87 98.03,124.12 v1(97.75,124.4) ; v1(140.12,124.5) 139.6,125.02 139.6,125.92 142.53,128.85 142.53,136.44 144.33,138.24 144.33,145.21 146.3,147.18 146.3,148.38 147.66,149.74 148.74,149.74 149.22,150.23 149.22,151.27 v1(149.51,151.55)
USB1_DP: length 121.3
  TOP w0.102: U2.R17 89.41,91 89.76,91.35 89.76,92.11 89.67,92.21 89.67,92.78 89.74,92.86 89.74,92.86 89.79,92.9
  TOP w0.114: v1(90.12,93.08) 90.1,93.06 89.95,93.06 89.79,92.9 ; L6.1 147.25,157.03 147.53,156.75 147.53,155.5 148.94,154.09 148.94,151.83 v1(148.66,151.55) ; v1(98.46,124.4) 98.36,124.49 98.36,124.98 98.55,125.17 124.93,125.17 125.08,125.32 137.37,125.32 138.35,124.34 139.32,124.34 v1(139.6,124.06)
  BOTTOM w0.114: v1(139.6,124.06) 139.32,124.34 139.32,126.04 142.25,128.97 142.25,136.55 144.06,138.35 144.06,145.33 146.02,147.29 146.02,148.5 147.55,150.02 148.63,150.02 148.94,150.34 148.94,151.27 v1(148.66,151.55) ; v1(98.46,124.4) 98.31,124.25 98.31,123.75 97.88,123.32 97.88,120.57 98.59,119.86 98.59,116.69 97.9,116 97.9,103.34 95.97,101.41 95.97,96.09 94.62,94.73 93.26,94.73 91.88,93.36 90.44,93.36 90.16,93.08 v1(90.12,93.08)
USB1_ID: length 125.9
  TOP w0.102: 88.94,92.9 88.94,92.84 88.87,92.78 88.87,92.11 89,91.99 89,91.41 88.6,91.01 U2.P17
  TOP w0.121: v1(146.79,160.12) 145.58,160.12 144.5,161.2 v1(140.25,161.2) ; 88.94,92.9 88.94,93.31 89.9,94.27 90.56,94.27 92.21,95.92 93.49,95.92 93.95,96.37 93.95,97.18 95.01,98.24 95.01,101.05 96.03,102.07 v1(104.81,102.07) ; R385.2 149.27,161.01 149.26,161.02 U30.3 148.43,160.32 v1(148.56,160.18)
  LY3 w0.133: v1(140.25,156.37) 139.42,155.55 133.2,155.55 130.72,153.07 v1(108.24,153.07)
  LY4 w0.133: v1(104.81,102.07) 106.52,103.78 106.52,151.35 v1(108.24,153.07)
  BOTTOM w0.121: v1(146.79,160.12) 146.98,160.31 148.44,160.31 v1(148.56,160.18) ; v1(140.25,156.37) v1(140.25,161.2)
USB1_OVRCURN: length 108
  TOP w0.121: v1(87.21,131) 88.27,131 89.38,132.12 93.36,132.12 94.68,133.44 117.13,133.44 118.27,132.29 v1(119.85,132.29) ; R412.2 145.64,150.85 U29.5 145.64,148.12 145.39,147.87 140.83,147.87 140.47,147.51 130.14,147.51 v1(130.06,147.43)
  BOTTOM w0.121: v1(87.21,131) 88.82,129.39 88.82,117.14 87.35,115.67 87.35,104.95 85.25,102.86 R410.2 ; v1(119.85,132.29) 119.85,132.68 123.28,136.1 123.28,143.8 126.91,147.43 v1(130.06,147.43)
VAUX1: length 276.1
  TOP w0.508: v1(103.01,138.7) 106.55,138.7 110.21,135.04 v1(113.45,135.04) ; v1(48.7,87.28) 48.81,87.39 v1(55.64,87.39) ; R502.1 117.32,141.1 v1(117.32,139.8) ; v1(51.85,31.79) 76.62,31.79 78.17,30.23 v1(79.44,30.23) 79.44,30.7 79.78,31.04 80.79,31.04 81.06,30.77 R474.2 ; v1(101.99,121.78) 101.84,121.63 91.5,121.63 88.96,119.09 73.72,119.09 73.65,119.16 v1(55.6,119.16)
  TOP w0.635: J19.16 118.97,24.36 117.96,25.37 v1(117.13,25.37)
  BOTTOM w0.508: v1(55.6,119.16) 55.76,119 55.76,95.54 55.41,95.19 55.41,91.34 55.76,90.98 55.76,87.51 v1(55.64,87.39) ; v1(113.45,135.04) 113.45,138.4 114.34,139.29 116.81,139.29 v1(117.32,139.8) ; v1(48.7,87.28) 48.7,86.65 48.59,86.53 48.59,81.76 51.16,79.19 51.16,74.47 54.24,71.38 54.24,60.92 53.89,60.57 v1(53.89,55) 54.14,54.75 54.14,50.35 51.85,48.07 v1(51.85,31.79) ; v1(103.01,138.7) 103.01,135.39 101.64,134.02 101.64,124.88 101.99,124.52 v1(101.99,121.78)
  BOTTOM w0.635: v1(117.13,25.37) 115.23,25.37 114.15,26.45 111.16,26.45 109.89,25.18 109.89,22.77 107.03,19.91 94.21,19.91 92.94,18.64 87.86,18.64 87.03,19.47 81.83,19.47 81.19,20.1 81.19,22.52 80.05,23.66 79.98,23.66 78.65,24.99 78.65,27.72 79.44,28.52 v1(79.44,30.23)
VAUX2: length 408
  TOP w0.508: v1(76.34,48.54) 80.34,48.54 81.15,47.73 87.98,47.73 88.62,48.36 99.49,48.36 v1(99.99,48.86) v1(114.59,48.86) 115.48,48.86 117.52,50.9 124.12,50.9 v1(125.58,52.36) 129.51,52.36 131.29,54.14 150.15,54.14 v1(150.28,54.01) ; v1(78.46,28.74) 79.41,28.74 80.17,29.5 81.34,29.5 81.6,29.25 R475.2 ; v1(17.88,41.06) 52.55,41.06 54.84,43.34 58.58,43.34 60.04,41.88 76.05,41.88 v1(76.81,42.65) ; 48.23,83.41 v1(46.58,85.06) ; 48.23,83.41 54.07,83.41 v1(56.23,85.57) ; 48.23,83.41 48.23,82.65 47.85,82.27 v1(22.2,82.27) ; FB20.2 124.37,140.56 124.37,137.58 125.96,135.99 144.88,135.99 v1(144.94,135.93)
  BOTTOM w0.508: v1(17.88,41.06) 16.17,42.77 16.17,45.69 16.61,46.14 16.61,62.46 22.2,68.05 v1(22.2,82.27) ; v1(99.99,48.86) 99.99,48.87 99.67,49.19 R68.2 ; FB8.2 51.35,91.91 50.38,90.94 49.22,90.94 46.58,88.3 v1(46.58,85.06) ; v1(78.46,28.74) 77.25,28.74 76.46,29.53 76.46,33.6 79.16,36.3 79.16,38.58 76.81,40.93 v1(76.81,42.65) 76.81,45.63 76.34,46.1 v1(76.34,48.54) ; v1(125.58,52.36) 125.58,23.66 J19.17 ; v1(144.94,135.93) 144.94,119.16 145.78,118.32 145.78,107.3 145.66,107.17 145.66,100.6 144.59,99.53 144.59,96.29 145.74,95.13 145.93,95.13 147.08,93.99 147.08,89.6 149.52,87.16 149.52,85.37 150.28,84.6 v1(150.28,54.01) ; FB2.2 v1(56.23,85.57)
  BOTTOM w0.635: v1(114.59,48.86) 114.59,55.09 FB6.2
VAUX33: length 211.2
  TOP w0.762: v1(144.18,135.23) 114.34,135.23 112.81,136.75 112.81,138.5 R504.1 ; J19.18 123.23,19.78 120.88,19.78 113.45,27.22 106.21,27.22 105.35,26.35 100.58,26.35 100.49,26.26 97.14,26.26 R463.1 ; v1(149.96,53.25) 131.61,53.25 129.83,51.47 v1(126.34,51.47)
  BOTTOM w0.762: v1(149.96,53.25) 149.52,53.7 149.52,84.29 148.55,85.25 148.55,86.73 146.32,88.96 146.32,93.67 145.69,94.3 145.5,94.3 143.7,96.1 143.7,99.88 144.69,100.87 144.69,108.16 144.89,108.36 144.89,117.03 145.02,117.17 145.02,117.94 144.18,118.78 v1(144.18,135.23) ; v1(126.34,51.47) 126.34,21.88 J19.18
VBCKUPBAT: length 16
  TOP w0.203: 92.35,38.14 91.95,37.73 91.31,37.73 90.85,37.26 90.85,36.77
  TOP w0.508: 92.35,38.14 94.13,38.14 98.07,42.07 TP26.1 BT1.1
VDAC: length 272.4
  TOP w0.508: v1(103.45,128.28) 109.23,128.28 110.88,126.62 115.41,126.62 115.57,126.47 118.85,126.47 121.13,128.75 125.83,128.75 128.35,126.24 130.68,126.24 130.77,126.15 140.31,126.15 141.83,124.62 145.01,124.62 145.45,124.18 v1(165.77,124.18) ; v1(121.07,36.04) 109.57,36.04 109.51,36.11 v1(108.88,36.11) R471.2 ; v1(110.53,55.66) 117.81,55.66 121.89,59.75 121.89,60.15 123.02,61.27 127.27,61.27 129.26,59.28 141.32,59.28 141.69,58.91 151.24,58.91 152.21,57.95 159.49,57.95 161.14,56.29 161.14,50.8 161.84,50.1 165.86,50.1 v1(166.66,50.9)
  BOTTOM w0.508: v1(166.66,50.9) 166.66,59.19 167.68,60.21 167.68,88.62 165.77,90.52 v1(165.77,124.18) ; v1(108.88,36.11) 108.88,53.25 110.53,54.9 v1(110.53,55.66) ; J19.14 121.58,31.6 121.58,35.53 v1(121.07,36.04) ; v1(103.45,128.28) 103.45,121.04 104.81,119.67 104.81,115.8 104.49,115.48 R498.2
VDIG1: length 301.5
  TOP w0.635: v1(126.97,141.77) 126.97,141.45 FB21.2
  TOP w0.762: J19.11 121.46,34.78 110.79,34.78 v1(110.53,34.52) ; v1(112.05,50.08) 111.61,49.63 99.48,49.63 99.09,49.25 88.24,49.25 87.54,48.55 81.57,48.55 80.78,49.34 73.04,49.34 72.59,49.79 72.26,50.12 70.8,50.12 70.26,50.65 70.05,50.65 69.95,50.76 66.4,50.76 65.66,50.02 59.78,50.02 59.47,50.33 v1(55.61,50.33) ; v1(127.04,130.97) 101.03,130.97 v1(100.52,130.47) ; v1(96.33,23.96) v1(103.92,23.96) ; v1(52.87,97) v1(56.53,97)
  LY3 w0.762: v1(100.52,130.47) 100.27,130.21 90.99,130.21 90.51,129.73 61.38,129.73 60.77,130.34 v1(53.12,130.34)
  BOTTOM w0.635: v1(127.04,130.97) 126.97,131.04 v1(126.97,141.77)
  BOTTOM w0.762: v1(112.05,50.08) R472.2 111.17,48.82 110.53,48.17 v1(110.53,34.52) 110.53,28.61 107.86,25.95 106.33,25.95 105.12,24.74 105.12,24.73 104.35,23.96 v1(103.92,23.96) ; v1(52.87,97) 52.72,96.85 52.72,96.2 51.57,95.06 51.57,94.12 FB7.2 ; v1(55.61,50.33) 55.61,50.89 55.08,51.43 55.08,59.27 55.28,59.47 55.28,71.79 52.23,74.84 52.23,78.4 53.43,79.59 55.1,79.59 56.23,80.72 FB1.2 57.24,81.83 57.49,82.07 57.49,82.5 57.49,82.51 57.49,85.23 57.14,85.58 57.14,88.1 56.53,88.71 56.53,91.35 56.17,91.71 56.17,94.87 56.53,95.23 v1(56.53,97) 56.53,117.39 57.07,117.92 57.07,119.26 53.12,123.2 v1(53.12,130.34) ; v1(96.33,23.96) 94.49,25.81 R464.1 ; FB3.2 128.12,130.97 v1(127.04,130.97)
VDIG2: length 272.9
  TOP w0.635: v1(108.18,50.96) 106.97,50.96 106.46,50.46 99.03,50.46 98.65,50.07 87.73,50.07 87.16,49.5 82.02,49.5 81.35,50.17 73.38,50.17 72.6,50.94 71.94,51.6 71.38,51.6 70.76,52.22 65.18,52.22 64.26,53.14 64.09,53.14 v1(63.6,53.63) v1(53.43,53.63) ; J19.12 122.97,33.75 114.4,33.75 111.42,30.77 v1(106.78,30.77) ; v1(50.2,100.11) v1(52.74,100.11) ; R476.1 91.36,26.37 91.73,26 92.26,26 92.31,25.95 92.32,25.95 93.08,25.18 v1(103.92,25.18) ; v1(104.91,62.49) 109.16,62.49 v1(109.19,62.46) v1(111.8,62.46) ; R497.1 98.14,115.73 98.46,116.05 98.46,119.67 98.08,120.05 92.54,120.05 v1(91.02,118.52)
  LY3 w0.635: v1(53.12,118.27) 74.38,118.27 75.4,119.29 82.43,119.29 83.2,118.52 v1(91.02,118.52)
  BOTTOM w0.635: v1(109.19,62.46) 109.19,57.82 108.18,56.81 v1(108.18,50.96) 108.18,47.47 107.23,46.52 107.23,31.22 v1(106.78,30.77) 106.78,28.04 v1(103.92,25.18) ; v1(53.12,118.27) 53.12,107.54 52.74,107.16 v1(52.74,106.46) v1(52.74,100.11) 52.74,98.04 51.89,97.19 51.89,96.79 50.8,95.69 50.74,95.69 49.92,94.88 R499.1 48.55,94.88 45.73,92.05 45.73,80.38 43.7,78.35 43.7,73.42 46.98,70.14 50.46,70.14 53.5,67.09 53.5,61.33 53.19,61.01 53.19,53.87 v1(53.43,53.63) ; R506.2 111.8,63.44 v1(111.8,62.46) ; v1(50.2,100.11) 49.72,100.59 R500.1 ; R503.2 v1(104.91,62.49) ; R507.1 62.8,55.03 63.6,54.23 v1(63.6,53.63)
